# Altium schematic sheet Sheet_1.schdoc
size 319 x 200 mm
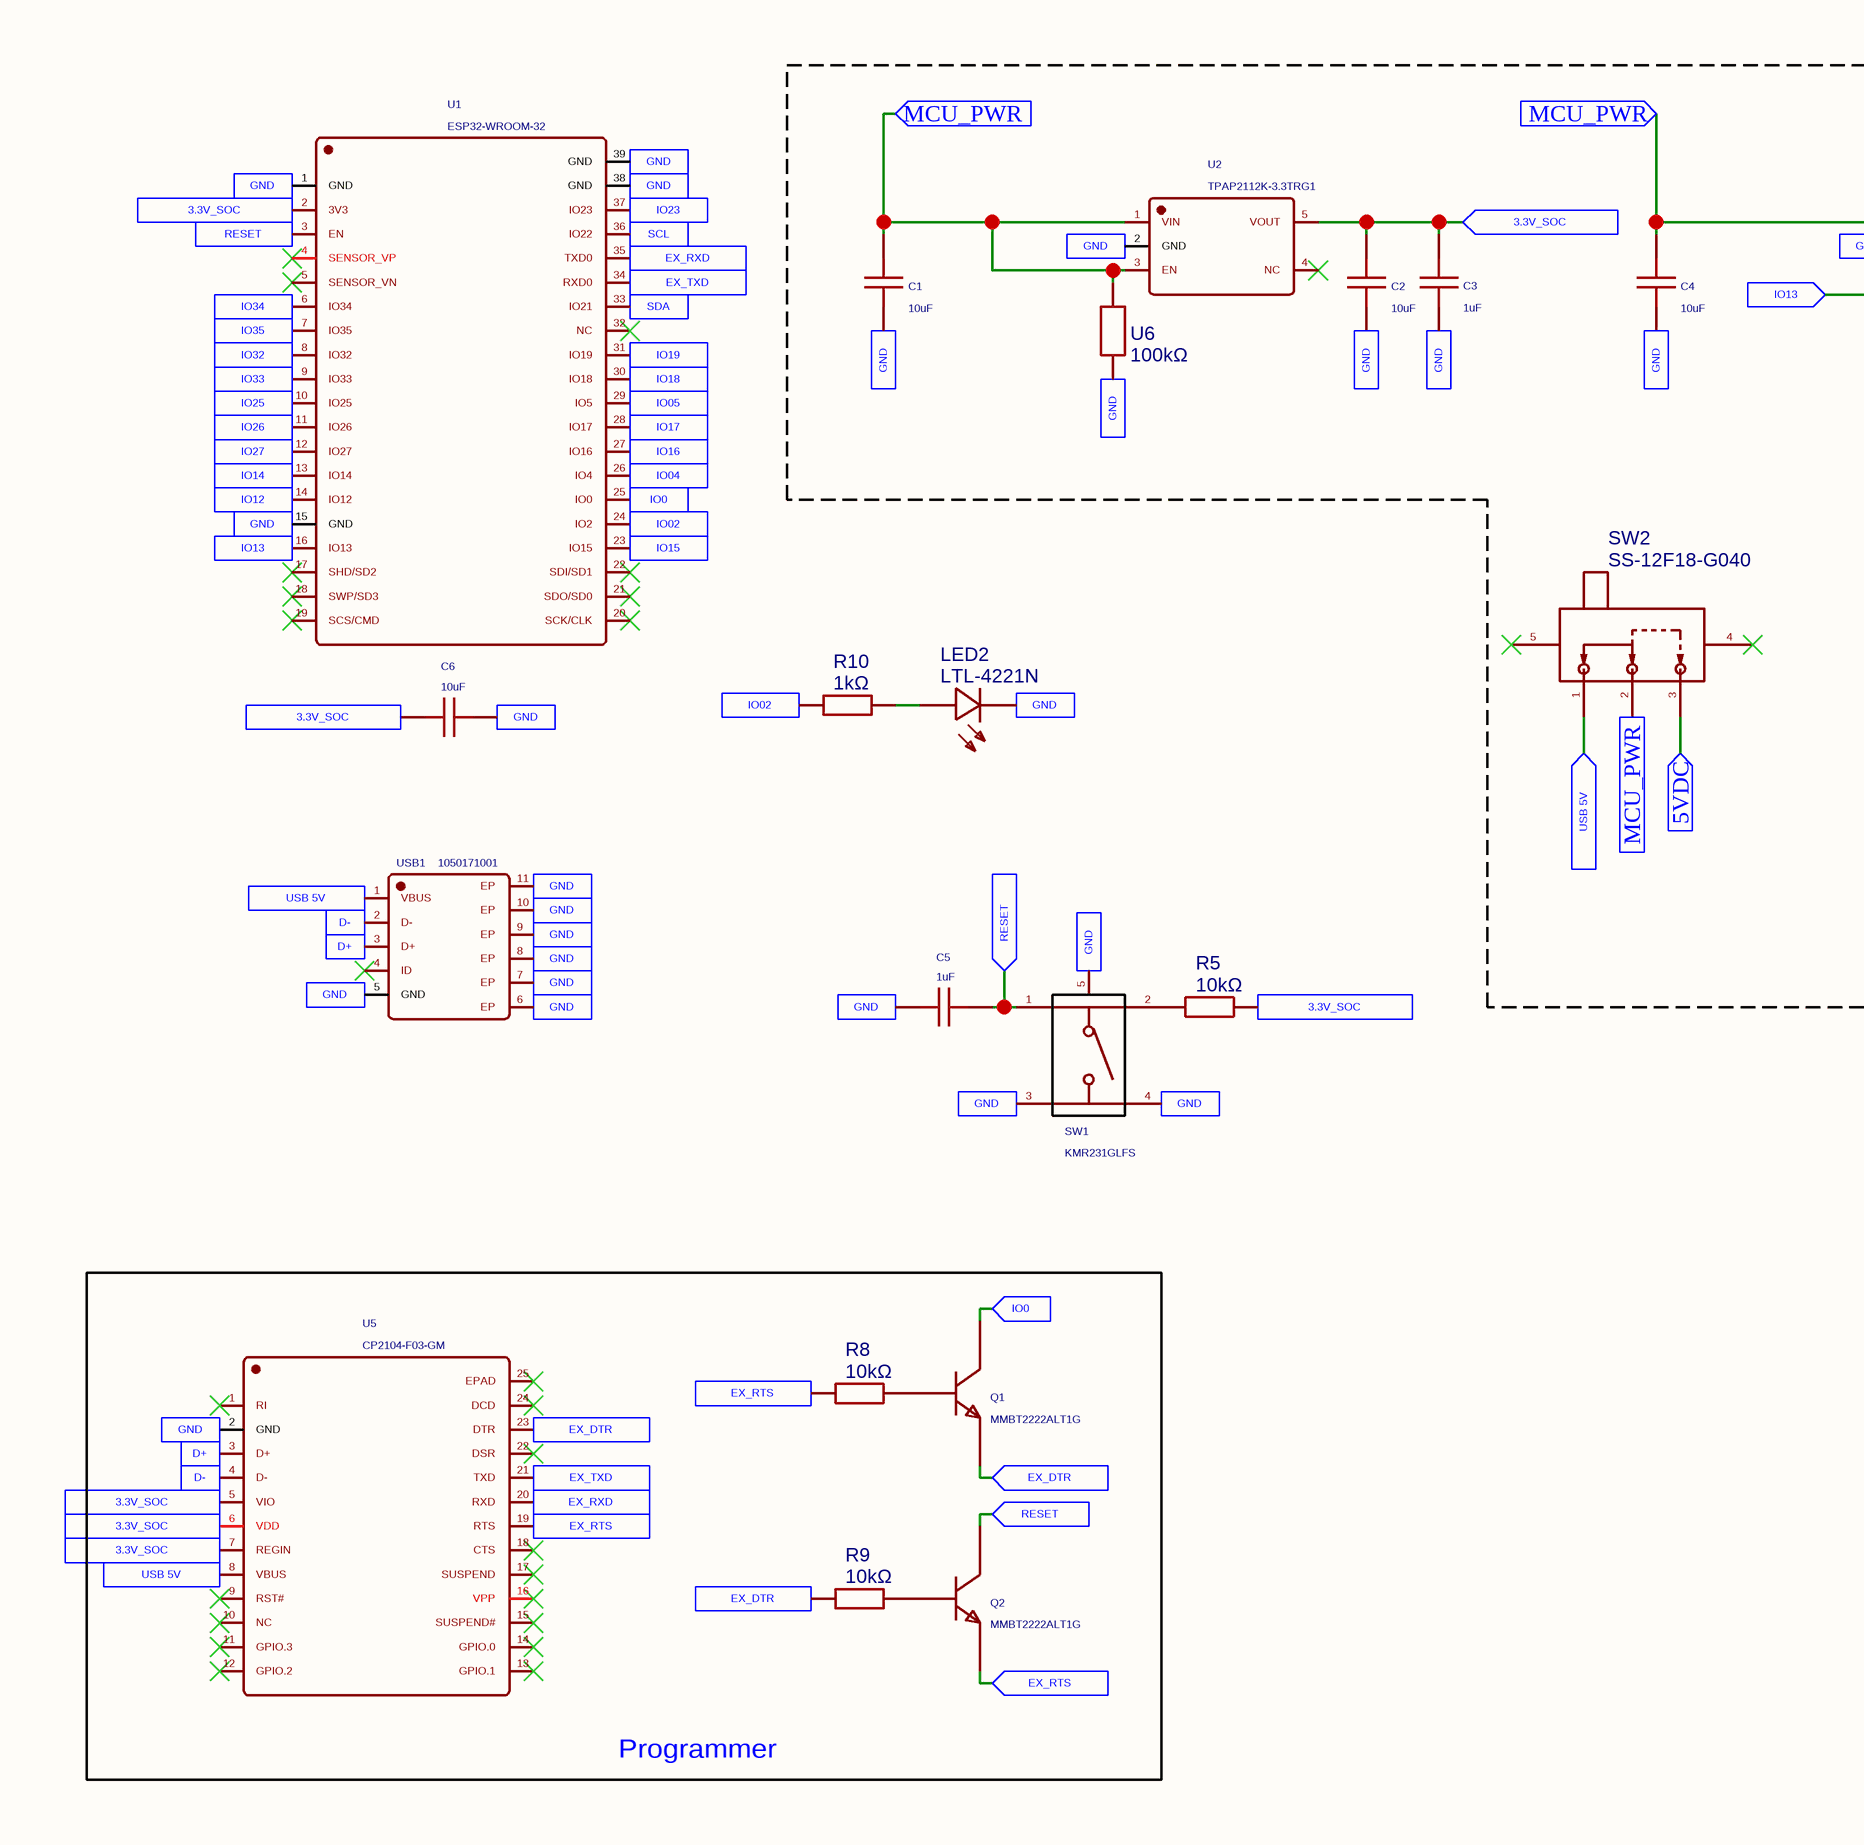
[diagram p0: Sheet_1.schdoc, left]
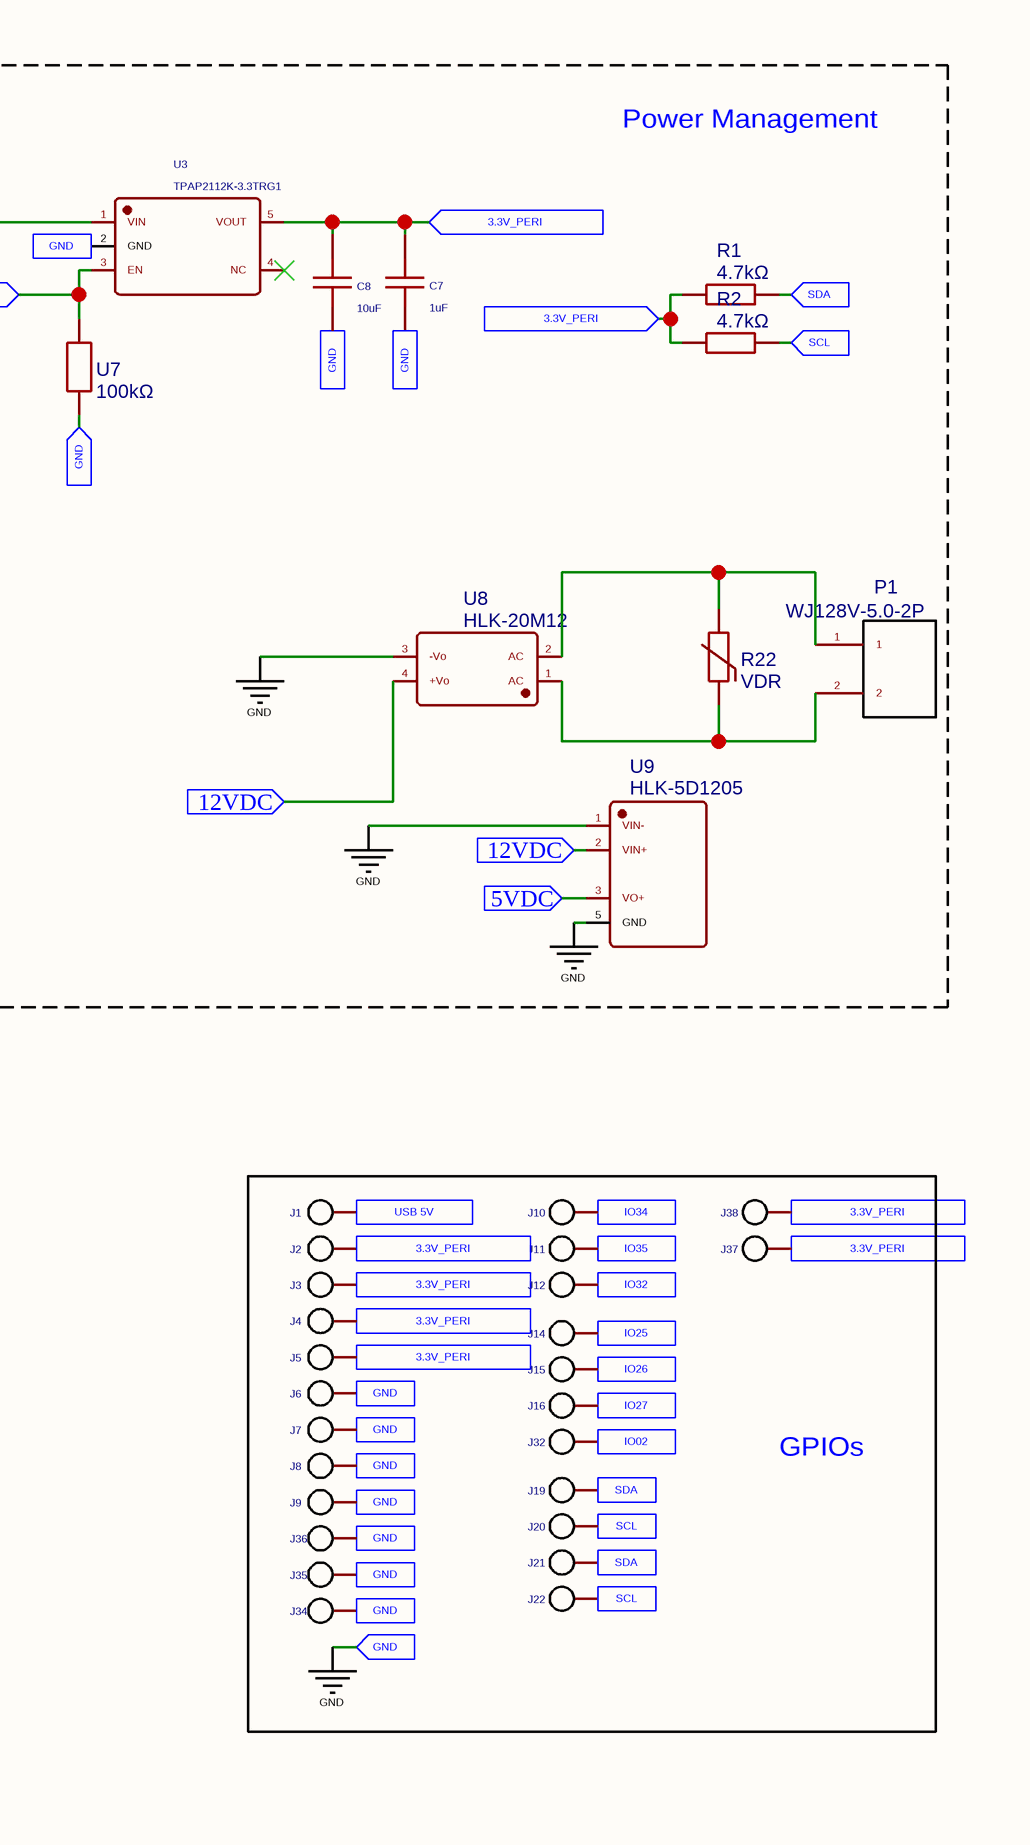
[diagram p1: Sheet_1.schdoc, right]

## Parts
C1  10uF  [C0603]
C2  10uF  [C0603]
C3  1uF  [C0603]
C4  10uF  [C0603]
C5  1uF  [C0603]
C6  10uF  [C0603]
C7  1uF  [C0603]
C8  10uF  [C0603]
J1  THT Pad  [THT PAD]  (value not drawn)
J2  THT Pad  [THT PAD]  (value not drawn)
J3  THT Pad  [THT PAD]  (value not drawn)
J4  THT Pad  [THT PAD]  (value not drawn)
J5  THT Pad  [THT PAD]  (value not drawn)
J6  THT Pad  [THT PAD]  (value not drawn)
J7  THT Pad  [THT PAD]  (value not drawn)
J8  THT Pad  [THT PAD]  (value not drawn)
J9  THT Pad  [THT PAD]  (value not drawn)
J10  THT Pad  [THT PAD]  (value not drawn)
J11  THT Pad  [THT PAD]  (value not drawn)
J12  THT Pad  [THT PAD]  (value not drawn)
J14  THT Pad  [THT PAD]  (value not drawn)
J15  THT Pad  [THT PAD]  (value not drawn)
J16  THT Pad  [THT PAD]  (value not drawn)
J19  THT Pad  [THT PAD]  (value not drawn)
J20  THT Pad  [THT PAD]  (value not drawn)
J21  THT Pad  [THT PAD]  (value not drawn)
J22  THT Pad  [THT PAD]  (value not drawn)
J32  THT Pad  [THT PAD]  (value not drawn)
J34  THT Pad  [THT PAD]  (value not drawn)
J35  THT Pad  [THT PAD]  (value not drawn)
J36  THT Pad  [THT PAD]  (value not drawn)
J37  THT Pad  [THT PAD]  (value not drawn)
J38  THT Pad  [THT PAD]  (value not drawn)
LED2  LTL-4221N  [LED-TH_BD3.0-P2.54-RD-RED]
P1  WJ128V-5.0-2P  [CONN-TH_2P-P5.00_WJ128V-5.0-2P]
Q1  MMBT2222ALT1G  [SOT-23-3_L2.9-W1.3-P1.90-LS2.4-BR]
Q2  MMBT2222ALT1G  [SOT-23-3_L2.9-W1.3-P1.90-LS2.4-BR]
R1  4.7kΩ  [RES-TH_BD2.3-L6.5-P10.50-D0.5]
R2  4.7kΩ  [RES-TH_BD2.3-L6.5-P10.50-D0.5]
R5  10kΩ  [RES-TH_BD2.3-L6.5-P10.50-D0.5]
R8  10kΩ  [RES-TH_BD2.3-L6.5-P10.50-D0.5]
R9  10kΩ  [RES-TH_BD2.3-L6.5-P10.50-D0.5]
R10  1kΩ  [RES-TH_BD2.3-L6.5-P10.50-D0.5]
R22  VDR  [RES-TH_L9.6-W5.6-P5.00-D0.7-S3.00]
SW1  KMR231GLFS  [KEY-SMD_KMR2XXGXXX]
SW2  SS-12F18-G040  [SW-TH_G-SWITCH_SS-12F18-G040]
U1  ESP32-WROOM-32  [WIFIM-SMD_ESP32-WROOM-32-N4]
U2  TPAP2112K-3.3TRG1  [SOT-23-5_L2.9-W1.6-P0.95-LS2.8-BR]
U3  TPAP2112K-3.3TRG1  [SOT-23-5_L2.9-W1.6-P0.95-LS2.8-BR]
U5  CP2104-F03-GM  [QFN-24_L4.0-W4.0-P0.50-BL-EP2.7]
U6  100kΩ  [RES-TH_BD2.5-L6.5-P10.50-D0.6]
U7  100kΩ  [RES-TH_BD2.5-L6.5-P10.50-D0.6]
U8  HLK-20M12  [PWRM-TH_HLK-20MXX]
U9  HLK-5D1205  [PWRM-TH_HLK-5DXXXX]
USB1  1050171001  [MICRO-USB-SMD_1050171001]

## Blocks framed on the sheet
Power Management: C1-C4 C7 C8 P1 R1 R2 R22 SW2 U2 U3 U6-U9
GPIOs: J1-J12 J14-J16 J19-J22 J32 J34-J38
Programmer: Q1 Q2 R8 R9 U5

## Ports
3.3V_PERI (in), 3.3V_SOC (in), 5VDC (in), 12VDC (in), D+ (in), D- (in), EX_DTR (in), EX_RTS (in), EX_RXD (in), EX_TXD (in), GND (in), IO0 (in), IO02 (in), IO04 (in), IO05 (in), IO12 (in), IO13 (in), IO14 (in), IO15 (in), IO16 (in), IO17 (in), IO18 (in), IO19 (in), IO23 (in), IO25 (in), IO26 (in), IO27 (in), IO32 (in), IO33 (in), IO34 (in), IO35 (in), MCU_PWR (in), RESET (in), SCL (in), SDA (in), USB 5V (in)

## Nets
GND: C1.2 C2.1 C3.1 C4.2 C5.2 C6.1 C7.1 C8.1 J6.1 J7.1 J8.1 J9.1 J34.1 J35.1 J36.1 LED2.1(-) SW1.3 SW1.4 SW1.5 U1.1(GND) U1.15(GND) U1.38(GND) U1.39(GND) U2.2(GND) U3.2(GND) U5.2(GND) U6.1 U7.1 U8.3(-Vo) U9.1(VIN-) U9.5(GND) USB1.5(GND) USB1.6(EP) USB1.7(EP) USB1.8(EP) USB1.9(EP) USB1.10(EP) USB1.11(EP) ; port GND
3.3V_PERI: C7.2 C8.2 J2.1 J3.1 J4.1 J5.1 J37.1 J38.1 R1.1 R2.1 U3.5(VOUT) ; port 3.3V_PERI
3.3V_SOC: C2.2 C3.2 C6.2 R5.2 U1.2(3V3) U2.5(VOUT) U5.5(VIO) U5.6(VDD) U5.7(REGIN) ; port 3.3V_SOC
5VDC: SW2.3 U9.3(VO+) ; port 5VDC
12VDC: U8.4(+Vo) U9.2(VIN+) ; port 12VDC
D+: U5.3(D+) USB1.3(D+) ; port D+
D-: U5.4(D-) USB1.2(D-) ; port D-
EX_DTR: Q1.2(E) R9.1 U5.23(DTR) ; port EX_DTR
EX_RTS: Q2.2(E) R8.1 U5.19(RTS) ; port EX_RTS
EX_RXD: U1.35(TXD0) U5.20(RXD) ; port EX_RXD
EX_TXD: U1.34(RXD0) U5.21(TXD) ; port EX_TXD
IO0: Q1.3(C) U1.25(IO0) ; port IO0
IO02: J32.1 R10.1 U1.24(IO2) ; port IO02
IO04: U1.26(IO4) ; port IO04
IO05: U1.29(IO5) ; port IO05
IO12: U1.14(IO12) ; port IO12
IO13: U1.16(IO13) U3.3(EN) U7.2 ; port IO13
IO14: U1.13(IO14) ; port IO14
IO15: U1.23(IO15) ; port IO15
IO16: U1.27(IO16) ; port IO16
IO17: U1.28(IO17) ; port IO17
IO18: U1.30(IO18) ; port IO18
IO19: U1.31(IO19) ; port IO19
IO23: U1.37(IO23) ; port IO23
IO25: J14.1 U1.10(IO25) ; port IO25
IO26: J15.1 U1.11(IO26) ; port IO26
IO27: J16.1 U1.12(IO27) ; port IO27
IO32: J12.1 U1.8(IO32) ; port IO32
IO33: U1.9(IO33) ; port IO33
IO34: J10.1 U1.6(IO34) ; port IO34
IO35: J11.1 U1.7(IO35) ; port IO35
MCU_PWR: C1.1 C4.1 SW2.2 U2.1(VIN) U2.3(EN) U3.1(VIN) U6.2 ; port MCU_PWR
RESET: C5.1 Q2.3(C) SW1.1 U1.3(EN) ; port RESET
SCL: J20.1 J22.1 R2.2 U1.36(IO22) ; port SCL
SDA: J19.1 J21.1 R1.2 U1.33(IO21) ; port SDA
USB 5V: J1.1 SW2.1 U5.8(VBUS) USB1.1(VBUS) ; port USB 5V
NetLED2_2: LED2.2(+) R10.2
NetP1_1: P1.1 R22.2 U8.2(AC)
NetP1_2: P1.2 R22.1 U8.1(AC)
NetQ1_1: Q1.1(B) R8.2
NetQ2_1: Q2.1(B) R9.2
NetR5_1: R5.1 SW1.2

Not connected (* = marked no-connect by the designer): SW2 4* 5*; U1 4(SENSOR_VP)* 5(SENSOR_VN)* 17(SHD/SD2)* 18(SWP/SD3)* 19(SCS/CMD)* 20(SCK/CLK)* 21(SDO/SD0)* 22(SDI/SD1)* 32(NC)*; U2 4(NC)*; U3 4(NC)*; U5 1(RI)* 9(RST#)* 10(NC)* 11(GPIO.3)* 12(GPIO.2)* 13(GPIO.1)* 14(GPIO.0)* 15(SUSPEND#)* 16(VPP)* 17(SUSPEND)* 18(CTS)* 22(DSR)* 24(DCD)* 25(EPAD)*; USB1 4(ID)*

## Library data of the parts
C1 C4 = 10uF: BOM_Manufacturer: Walsin(华新科); BOM_Manufacturer Part: 0603X106K100CT; Contributor: LCSC; nameAlias: Capacitance
C2 C6 C8 = 10uF: BOM_Manufacturer: SANYEAR(叁叶源); BOM_Manufacturer Part: C0603X5R106M160NT; nameAlias: Capacitance; Contributor: LCSC
C3 C5 C7 = 1uF: BOM_Manufacturer: YAGEO(国巨); BOM_Manufacturer Part: CC0603KRX7R6BB105; nameAlias: Capacitance; Contributor: LCSC
J1-J12 J14-J16 J19-J22 J32 J34-J38 = THT Pad: Contributor: menguy
LED2 = LTL-4221N: BOM_Manufacturer: LITEON(光宝); Contributor: LCSC
P1 = WJ128V-5.0-2P: BOM_Manufacturer: KANGNEX(康奈克斯电气)
Q1 Q2 = MMBT2222ALT1G: BOM_Manufacturer: onsemi(安森美)
R1 R2 = 4.7kΩ: BOM_Manufacturer: CCO(千志电子); BOM_Manufacturer Part: CF1/4W-4.7KΩ±5% T; Resistance (Ohms): 4.7K; nameAlias: Resistance; Contributor: LCSC
R5 R8 R9 = 10kΩ: BOM_Manufacturer: CCO(千志电子); BOM_Manufacturer Part: MF1/4W-10KΩ±1% T; Resistance (Ohms): 10K; nameAlias: Resistance; Contributor: LCSC
R10 = 1kΩ: BOM_Manufacturer: CCO(千志电子); BOM_Manufacturer Part: CF1/4W-1KΩ±5% T; Resistance (Ohms): 1K; nameAlias: Resistance; Contributor: LCSC
R22 = VDR: BOM_Manufacturer: VDR(嵩隆); BOM_Manufacturer Part: VDR-07D241K; nameAlias: Value; Contributor: LCSC
SW1 = KMR231GLFS: BOM_Manufacturer: C&K; Contributor: LCSC
SW2 = SS-12F18-G040: BOM_Manufacturer: G-Switch(品赞); Contributor: LCSC
U1 = ESP32-WROOM-32: BOM_Manufacturer: ESPRESSIF(乐鑫); BOM_Manufacturer Part: ESP32-WROOM-32-N4; Contributor: LCSC
U2 U3 = TPAP2112K-3.3TRG1: BOM_Manufacturer: TECH PUBLIC(台舟); Contributor: lcsc
U5 = CP2104-F03-GM: BOM_Manufacturer: SILICON LABS(芯科); BOM_Manufacturer Part: CP2104-F03-GMR
U6 U7 = 100kΩ: BOM_Manufacturer: 华星机电; BOM_Manufacturer Part: RI40-1/4W-100KΩ±1%T; Contributor: lcsc; nameAlias: Resistance
U8 = HLK-20M12: BOM_Manufacturer: HI-LINK(海凌科); Contributor: LCSC
U9 = HLK-5D1205: BOM_Manufacturer: HI-LINK(海凌科); Contributor: LCSC
USB1 = 1050171001: BOM_Manufacturer: MOLEX; Contributor: LCSC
